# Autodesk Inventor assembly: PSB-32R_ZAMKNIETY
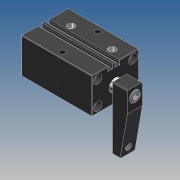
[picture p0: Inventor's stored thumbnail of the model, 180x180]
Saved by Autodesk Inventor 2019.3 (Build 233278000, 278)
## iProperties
Created: 2010-02
Part Number: PSB-32R_ZAMKNIETY
Material: Ogólny
Document SubType Name: Assembly
Designer: CADENGINEERING4
Sending System: PRO/ENGINEER BY PARAMETRIC TECHNOLOGY CORPORATION, 2007170
Preprocessor: PRO/ENGINEER BY PARAMETRIC TECHNOLOGY CORPORATION, 2007170
Title: PSB-32_ASM
Author: Administrator
Revision Number: 1LAST_VERSION
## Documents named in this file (6)
- E:\SERWER_ZAPAS\Pneumatic\PSB PNEUMATIC SWING\PSB-32\PSB-32R_ZAMKNIETY.iam
- E:\SERWER_ZAPAS\Pneumatic\PSB PNEUMATIC SWING\PSB-32\PSB-32BT.ipt
- E:\SERWER_ZAPAS\Pneumatic\PSB PNEUMATIC SWING\PSB-32\PSB-32HSG.ipt
- E:\SERWER_ZAPAS\Pneumatic\PSB PNEUMATIC SWING\PSB-32\PSB-32HG.ipt
- E:\SERWER_ZAPAS\Pneumatic\PSB PNEUMATIC SWING\PSB-32\PSB-32YB.ipt
- E:\SERWER_ZAPAS\Pneumatic\PSB PNEUMATIC SWING\PSB-32\M8X20.ipt
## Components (5 placed, 5 different names)
1. PSB-32BT_0 — Zestawiające:1, Kątowe:1
2. PSB-32HSG_1 — Zestawiające:1, Zestawiające:2, Zestawiające:3, Zestawiające:6
3. PSB-32HG_2 — Zestawiające:6
4. PSB-32YB_3 — Zestawiające:2, Zestawiające:3, Zestawiające:4, Zestawiające:5, Kątowe:1
5. M8X20_4 — Zestawiające:4, Zestawiające:5
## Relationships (7: Mate 6, Angle 1)
- Zestawiające:1 [Mate]: PSB-32BT_0 ↔ PSB-32HSG_1
- Zestawiające:2 [Mate]: PSB-32HSG_1 ↔ PSB-32YB_3
- Zestawiające:3 [Mate]: PSB-32HSG_1 ↔ PSB-32YB_3
- Zestawiające:4 [Mate]: PSB-32YB_3 ↔ M8X20_4
- Zestawiające:5 [Mate]: PSB-32YB_3 ↔ M8X20_4
- Kątowe:1 [Angle]: PSB-32BT_0 ↔ PSB-32YB_3
- Zestawiające:6 [Mate]: PSB-32HSG_1 ↔ PSB-32HG_2
